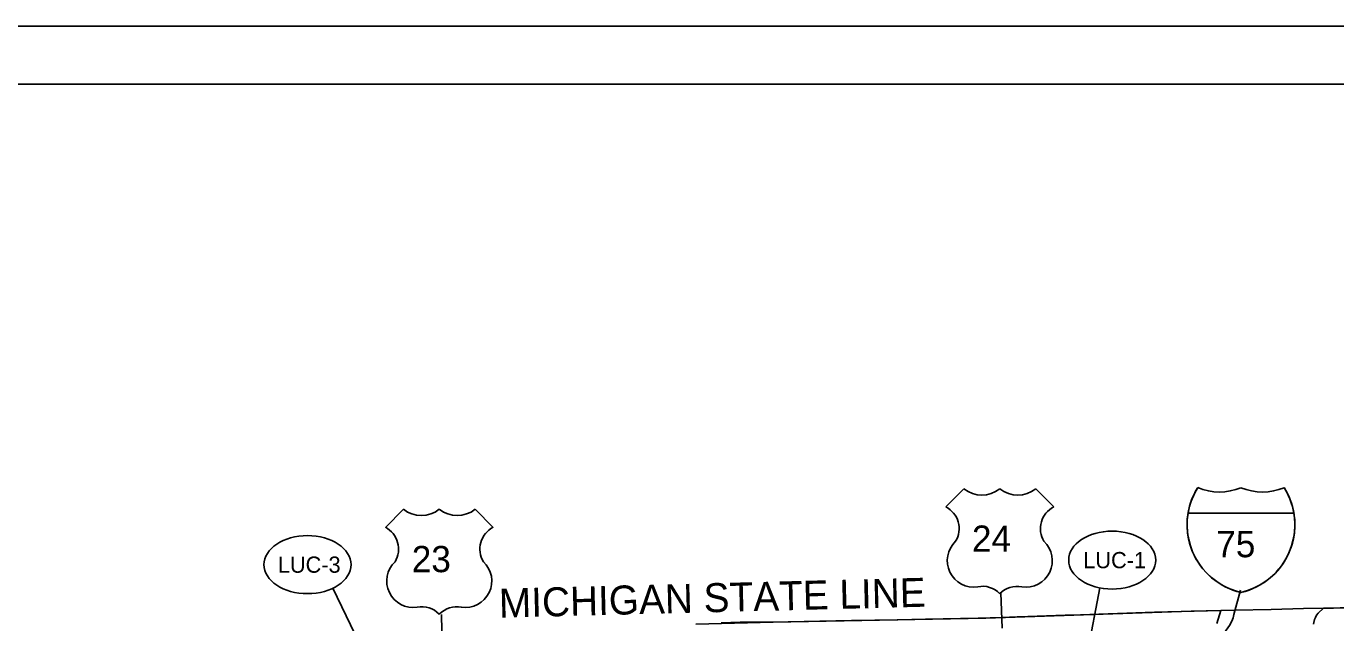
# Model space of a CAD drawing. Extents: x 0 to 750, y 0 to 507.
# Drawn here: x 180.7 to 406.4, y 337.1 to 440 of the extents above; entities that cross this region are included whole.
import ezdxf

# ---------------------------------------------------------------- set-up
doc = ezdxf.new("R2010")
doc.units = 0
for name, color, linetype in [('DV_X_Corp_Line', 7, 'Continuous'), ('GM_X_Adjacent_County_Text', 7, 'Continuous'), ('GM_X_Corporation_Text', 7, 'Continuous'), ('GM_X_County', 7, 'Continuous'), ('GM_X_Interstate_Route', 7, 'Continuous'), ('GM_X_US_Route', 7, 'Continuous'), ('SH_Border', 7, 'Continuous'), ('SH_Cut_Line', 7, 'Continuous'), ('SH_Data', 7, 'Continuous')]:
    doc.layers.add(name, color=color, linetype=linetype)

msp = doc.modelspace()

# ---------------------------------------------------------------- linework, layer by layer
at = {"layer": 'DV_X_Corp_Line'}
for points in [[(296.12, 336.86), (309.48, 337.24), (346.11, 337.93), (381.49, 339.13), (386.6, 339.24), (385.93, 336.98)], [(402.55, 336.9), (402.61, 337.18), (402.75, 337.7), (402.93, 338.05), (403.12, 338.44), (403.4, 338.77), (404.28, 339.61), (412.85, 339.79)]]:
    msp.add_lwpolyline(points, dxfattribs=at)
at = {"layer": 'GM_X_Corporation_Text'}
for p, q in [((342.33, 360.2), (339.22, 357.09)), ((342.33, 360.2), (339.22, 357.09)), ((357.81, 357.09), (354.7, 360.2)), ((357.81, 357.09), (354.7, 360.2)), ((245.74, 356.68), (242.63, 353.57)), ((245.74, 356.68), (242.63, 353.57)), ((261.21, 353.57), (258.1, 356.68)), ((261.21, 353.57), (258.1, 356.68)), ((380.96, 356.04), (399.2, 356.04)), ((399.2, 356.04), (380.96, 356.04)), ((399.2, 356.04), (380.96, 356.04))]:
    msp.add_line(p, q, dxfattribs=at)
for centre, radius, start, end in [((345.42, 364.13), 5, 231.813, 308.187), ((345.42, 364.13), 5, 231.813, 308.187), ((351.61, 364.13), 5, 231.813, 308.187), ((351.61, 364.13), 5, 231.813, 308.187), ((392.78, 354.03), 11.99, 147.8216, 256.9941), ((392.03, 354.24), 11.22, 146.654, 170.759), ((386.35, 369.23), 9.57, 247.0848, 292.9105), ((386.35, 369.23), 9.57, 247.0848, 292.9105), ((387.38, 354.03), 11.99, 283.0065, 32.1787), ((393.8, 369.23), 9.57, 247.0916, 292.9084), ((393.8, 369.23), 9.57, 247.0916, 292.9084), ((387.38, 354.03), 11.99, 9.6475, 32.179), ((248.83, 360.61), 5, 231.813, 308.187), ((248.83, 360.61), 5, 231.813, 308.187), ((255.01, 360.61), 5, 231.813, 308.187), ((255.01, 360.61), 5, 231.813, 308.187), ((337.28, 353.34), 4.23, 329.1175, 62.6108), ((337.28, 353.34), 4.23, 329.1175, 62.6108), ((359.75, 353.34), 4.23, 117.3892, 210.8825), ((359.75, 353.34), 4.23, 117.3892, 210.8825), ((392.78, 354.03), 11.99, 170.3514, 256.9967), ((387.4, 354.02), 11.97, 282.7667, 9.6898), ((240.68, 349.82), 4.23, 329.1175, 62.6108), ((240.68, 349.82), 4.23, 329.1175, 62.6108), ((263.15, 349.82), 4.23, 117.3892, 210.8825), ((263.15, 349.82), 4.23, 117.3892, 210.8825), ((344.02, 347.83), 4.56, 133.0046, 278.7282), ((344.02, 347.83), 4.56, 133.0046, 278.7282), ((353.01, 347.83), 4.56, 261.2718, 46.9954), ((353.01, 347.83), 4.56, 261.2718, 46.9954), ((247.42, 344.31), 4.56, 133.0046, 278.7282), ((247.42, 344.31), 4.56, 133.0046, 278.7282), ((256.41, 344.31), 4.56, 261.2718, 46.9954), ((256.41, 344.31), 4.56, 261.2718, 46.9954), ((345.55, 339.33), 4.08, 43.4177, 101.8742), ((345.55, 339.33), 4.08, 43.4177, 101.8742), ((351.56, 339.06), 4.33, 79.9613, 134.7468), ((351.56, 339.06), 4.33, 79.9613, 134.7468), ((248.95, 335.81), 4.08, 43.4177, 101.8742), ((248.95, 335.81), 4.08, 43.4177, 101.8742), ((254.97, 335.54), 4.33, 79.9613, 134.7468), ((254.97, 335.54), 4.33, 79.9613, 134.7468)]:
    msp.add_arc(centre, radius, start, end, dxfattribs=at)
at = {"layer": 'GM_X_County'}
msp.add_lwpolyline([(300.49, 337.08), (303.78, 337.22), (309.32, 337.24), (322.94, 337.49), (330.95, 337.64), (335.7, 337.73), (344.8, 337.93), (348.87, 338.03), (351.52, 338.12), (351.76, 338.13), (359.77, 338.4), (360.79, 338.43), (375.18, 338.92), (386.6, 339.24), (389.04, 339.29), (395.26, 339.42), (400.87, 339.55), (406.02, 339.64), (412.02, 339.77)], dxfattribs=at)
at = {"layer": 'GM_X_Interstate_Route'}
msp.add_lwpolyline([(385.15, 333.85), (385.5, 334.07), (386.13, 334.43), (386.65, 334.84), (387.19, 335.4), (387.55, 335.84), (388.1, 336.62), (388.5, 337.4), (388.71, 337.95), (388.83, 338.54), (389.98, 342.75)], dxfattribs=at)
at = {"layer": 'GM_X_US_Route'}
for points in [[(348.93, 336.2), (348.72, 342.29)], [(252.55, 327.09), (252.28, 338.57)]]:
    msp.add_lwpolyline(points, dxfattribs=at)
at = {"layer": 'SH_Border'}
msp.add_lwpolyline([(30, 430), (670, 430), (670, 10), (30, 10)], close=True, dxfattribs=at)
at = {"layer": 'SH_Cut_Line'}
msp.add_lwpolyline([(0, 0), (680, 0), (680, 440), (0, 440)], close=True, dxfattribs=at)
at = {"layer": 'SH_Data'}
for p, q in [((233.6, 343.09), (253.72, 301.31)), ((365.78, 343.12), (357.52, 300.67))]:
    msp.add_line(p, q, dxfattribs=at)
for centre in [(229.21, 347.14), (367.89, 347.92)]:
    msp.add_ellipse(centre, major_axis=(7.5, 0), ratio=0.666667, dxfattribs=at)

# ---------------------------------------------------------------- texts
at = {"layer": 'GM_X_Adjacent_County_Text'}
msp.add_text('MICHIGAN STATE LINE', height=5, rotation=1.4885, dxfattribs=at).set_placement((262.26, 337.98))
at = {"layer": 'GM_X_Corporation_Text'}
for s, p in [('24', (343.72, 349.36)), ('75', (385.82, 348.42)), ('23', (247.18, 345.84))]:
    msp.add_text(s, height=4.528, dxfattribs=at).set_placement(p)
at = {"layer": 'SH_Data'}
for s, p in [('LUC-3', (224.1, 345.74)), ('LUC-1', (362.9, 346.52))]:
    msp.add_text(s, height=2.8, dxfattribs=at).set_placement(p)

doc.saveas('drawing.dxf')
